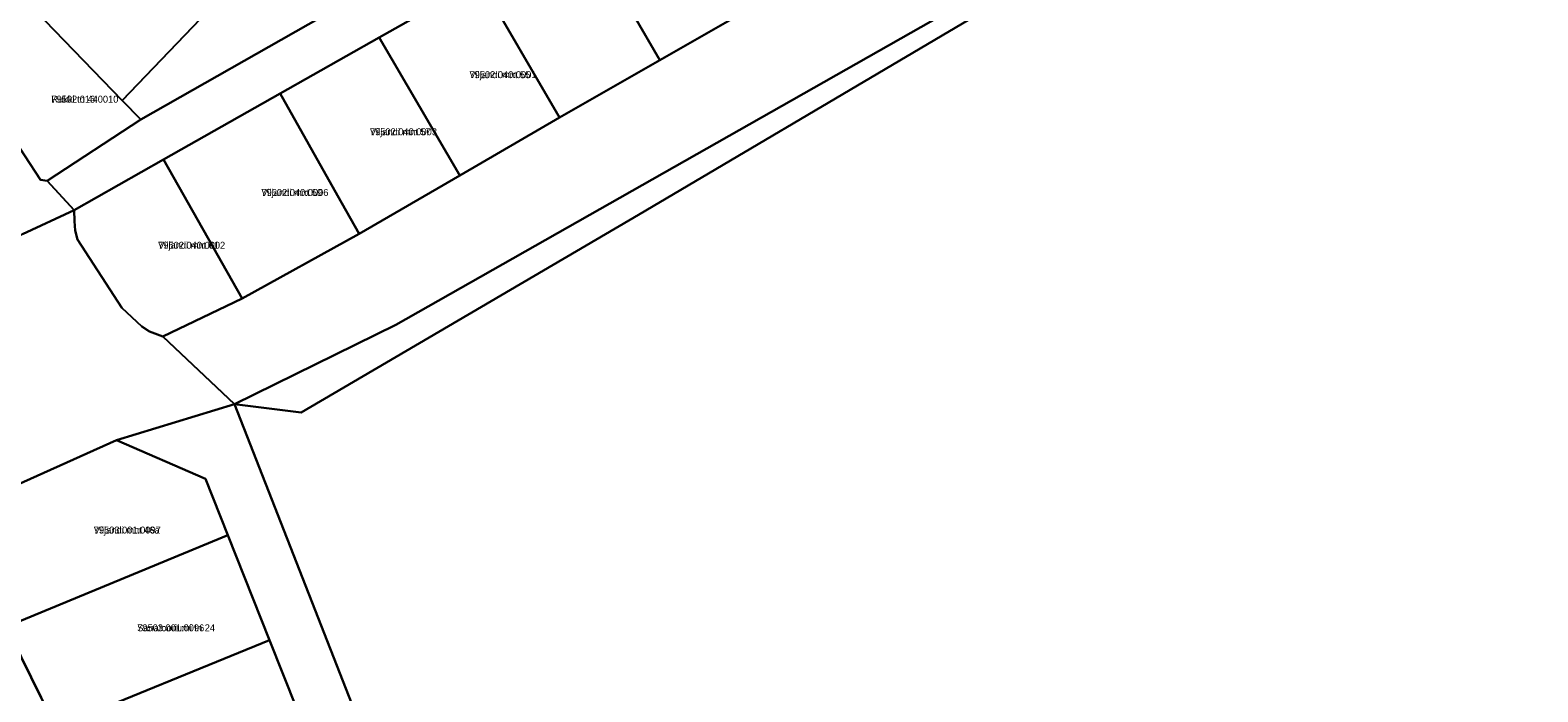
# Model space of a CAD drawing. Extents: x 643847 to 663718, y 6468443 to 6482775.
# Drawn here: x 656994 to 657320.2, y 6472833.9 to 6472977.1 of the extents above; entities that cross this region are included whole.
import ezdxf

# ---------------------------------------------------------------- set-up
doc = ezdxf.new("R2010")
doc.units = 0
for name, color, linetype in [('L_AADRESS', 7, 'Continuous'), ('PIIR', 7, 'Continuous'), ('TUNNUS', 7, 'Continuous')]:
    doc.layers.add(name, color=color, linetype=linetype)

msp = doc.modelspace()

# ---------------------------------------------------------------- linework, layer by layer
at = {"layer": 'PIIR'}
for points in [[(657360.81, 6473103.15), (657383.22, 6473116.43), (657383.38, 6473118.7), (657395.55, 6473096.29), (657073.12, 6472913.32), (657038.22, 6472896.22), (657022.68, 6472910.82), (657039.85, 6472919.08), (657065.2, 6472933.01), (657086.93, 6472945.64), (657108.54, 6472958.21), (657130.25, 6472970.63), (657151.94, 6472983.05), (657182.35, 6473000.45), (657195.67, 6473008.07), (657215.59, 6473019.56), (657235.96, 6473031.29), (657256.75, 6473043.27), (657277.59, 6473055.16), (657298.44, 6473067.05), (657319.18, 6473079.12), (657339.98, 6473091.43)], [(657052.62, 6472894.35), (657038.22, 6472896.22), (657073.12, 6472913.32), (657395.55, 6473096.29), (657386.1, 6473090.11), (657313.18, 6473048.04), (657125.59, 6472937.14)], [(657093.18, 6472755.82), (657038.22, 6472896.22), (657052.62, 6472894.35), (657125.59, 6472937.14), (657313.18, 6473048.04), (657352.18, 6472980.82), (657436.05, 6473029.47), (657630.21, 6472764.71), (657635.39, 6472768.4), (657646.35, 6472753.34), (657584.79, 6472713.27), (657571.56, 6472704.34), (657535.11, 6472679.69), (657459, 6472635.48), (657391.69, 6472593.48), (657354.3, 6472568.92), (657336.92, 6472557.13), (657235.57, 6472487.84)], [(657150.38, 6473032.82), (657157.55, 6473025.54), (657134.9, 6473012.34), (657113.1, 6473000.1), (657091.29, 6472987.86), (657069.54, 6472975.55), (657048.09, 6472963.39), (657022.85, 6472949.1), (657003.52, 6472938.13), (656997.72, 6472944.48), (657017.93, 6472957.8), (657056.85, 6472979.85), (657079.47, 6472992.67), (657099.04, 6473003.75), (657119.05, 6473015.09)], [(657130.25, 6472970.63), (657113.1, 6473000.1), (657134.9, 6473012.34), (657146.96, 6472991.6), (657151.94, 6472983.05)], [(657005.09, 6473009.44), (657008.64, 6473004.81), (657025.22, 6472986.32), (657030.86, 6472979.55), (657013.94, 6472961.91), (656988.8, 6472987.94)], [(657108.54, 6472958.21), (657091.29, 6472987.86), (657113.1, 6473000.1), (657130.25, 6472970.63)], [(657017.93, 6472957.8), (657013.94, 6472961.91), (657030.86, 6472979.55), (657025.22, 6472986.32), (657045.68, 6472999.21), (657056.85, 6472979.85)], [(656988.8, 6472987.94), (657013.94, 6472961.91), (657017.93, 6472957.8), (656997.72, 6472944.48), (656996.22, 6472944.71), (656979.24, 6472970.7), (656979.35, 6472975.6)], [(657086.93, 6472945.64), (657069.54, 6472975.55), (657091.29, 6472987.86), (657108.54, 6472958.21)], [(657065.2, 6472933.01), (657060.51, 6472941.33), (657048.09, 6472963.39), (657069.54, 6472975.55), (657086.93, 6472945.64)], [(657039.85, 6472919.08), (657022.85, 6472949.1), (657048.09, 6472963.39), (657060.51, 6472941.33), (657065.2, 6472933.01)], [(657039.85, 6472919.08), (657022.68, 6472910.82), (657019.82, 6472911.92), (657018.17, 6472912.98), (657013.86, 6472917.05), (657004.26, 6472931.85), (657003.71, 6472933.76), (657003.62, 6472935.78), (657003.52, 6472938.13), (657022.85, 6472949.1)], [(657093.18, 6472755.82), (657235.57, 6472487.84), (657231.32, 6472484.94), (657223.76, 6472479.25), (657216.94, 6472491.07), (657207.18, 6472510.11), (657196.24, 6472531.44), (657185.69, 6472552.27), (657174.26, 6472574.34), (657158.08, 6472605.96), (657154.31, 6472613.25), (657140.47, 6472640.25), (657127.14, 6472666.27), (657123.03, 6472674.24), (657109.27, 6472701.09), (657099.11, 6472694.96), (657046, 6472802.56), (657059.95, 6472809.44), (657057.74, 6472815.02), (657045.8, 6472845.14), (657036.79, 6472867.87), (657031.97, 6472880.06), (657012.68, 6472888.39), (657038.22, 6472896.22)], [(656976.83, 6472872.3), (657012.68, 6472888.39), (657031.97, 6472880.06), (657036.79, 6472867.87), (656988.81, 6472848)], [(656963.88, 6472866.48), (656976.83, 6472872.3), (657018.01, 6472788.74), (656996.69, 6472778.18), (656974.29, 6472767.12), (657029.71, 6472655.15), (657010.8, 6472644.33), (656995.54, 6472635.57), (656987, 6472651.64), (656986.74, 6472652.13), (656937.91, 6472743.17), (656925.7, 6472765.93), (656891.04, 6472833.77)], [(656988.81, 6472848), (657036.79, 6472867.87), (657045.8, 6472845.14), (656999.54, 6472826.22)], [(656999.54, 6472826.22), (657045.8, 6472845.14), (657057.74, 6472815.02), (657059.95, 6472809.44), (657046, 6472802.56), (657018.01, 6472788.74)]]:
    msp.add_lwpolyline(points, close=True, dxfattribs=at)
for points in [[(656979.24, 6472970.7), (656996.22, 6472944.71), (656997.72, 6472944.48), (657003.52, 6472938.13), (656992.36, 6472932.95)], [(656729.14, 6472803.32), (656804.01, 6472845.98), (656820.68, 6472852.38), (656850.39, 6472863.78), (656874.56, 6472873.06), (656890.03, 6472879), (656922, 6472892.84), (656941.27, 6472901.18), (656949.99, 6472904.95), (656962.74, 6472913.38), (656992.36, 6472932.95), (657003.52, 6472938.13), (657003.62, 6472935.78), (657003.71, 6472933.76), (657004.26, 6472931.85), (657013.86, 6472917.05), (657018.17, 6472912.98), (657019.82, 6472911.92), (657022.68, 6472910.82), (657038.22, 6472896.22), (657012.68, 6472888.39), (656976.83, 6472872.3), (656963.88, 6472866.48), (656891.04, 6472833.77)]]:
    msp.add_lwpolyline(points, dxfattribs=at)

# ---------------------------------------------------------------- texts
at = {"layer": 'L_AADRESS'}
for s, p in [('Viljandi mnt 55', (657089.04, 6472966.73)), ('Rukki tn 44', (656998.59, 6472961.43)), ('Viljandi mnt 57', (657067.51, 6472954.38)), ('Viljandi mnt 59', (657044.03, 6472941.23)), ('Viljandi mnt 61', (657021.69, 6472929.82)), ('Viljandi mnt 46a', (657007.76, 6472868.2)), ('Sanatooriumi tn 24', (657017.16, 6472847.04))]:
    msp.add_text(s, height=1.5, dxfattribs=at).set_placement(p)
at = {"layer": 'TUNNUS'}
for s, p in [('79502:040:0001', (657089.04, 6472966.73)), ('79502:016:0010', (656998.59, 6472961.43)), ('79502:040:0003', (657067.51, 6472954.38)), ('79502:040:0006', (657044.03, 6472941.23)), ('79502:040:0002', (657021.69, 6472929.82)), ('79503:001:0097', (657007.76, 6472868.2)), ('79503:001:0096', (657017.16, 6472847.04))]:
    msp.add_text(s, height=1.5, dxfattribs=at).set_placement(p)

doc.saveas('drawing.dxf')
